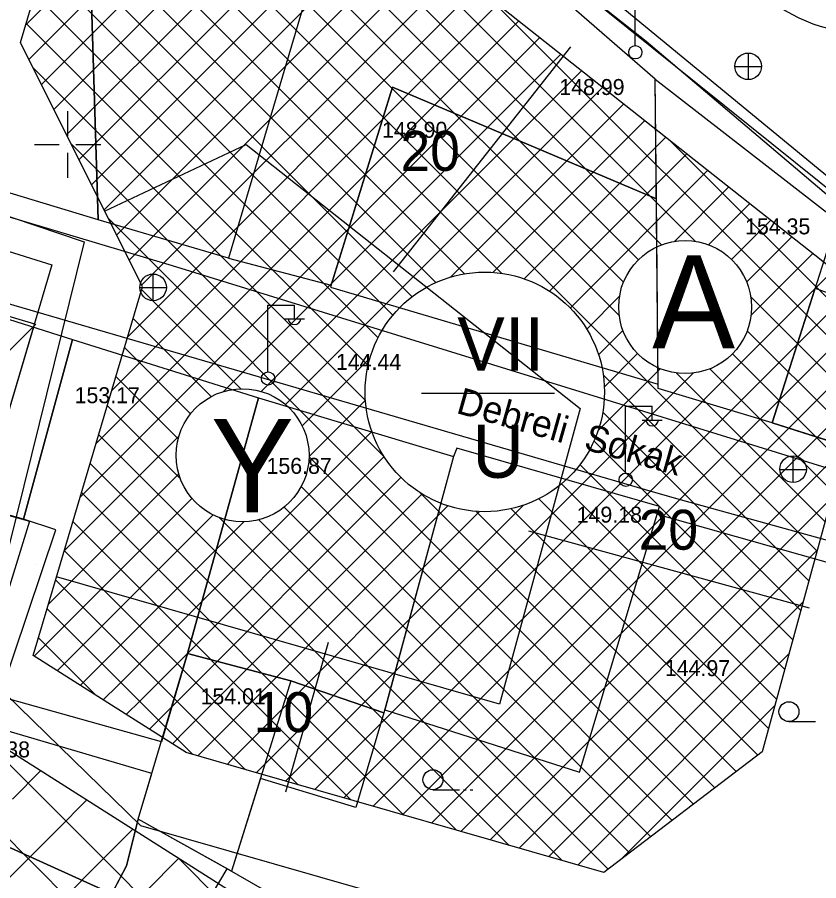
# Model space of a CAD drawing. Extents: x 419677 to 421689, y 4450851 to 4452923.
# Drawn here: x 420331.7 to 420392, y 4452030.4 to 4452095.3 of the extents above; entities that cross this region are included whole.
import ezdxf

# ---------------------------------------------------------------- set-up
doc = ezdxf.new("R2010")
doc.units = 0
for name, color, linetype in [('AA_HH', 7, 'Continuous'), ('Level 10', 7, 'Continuous'), ('Level 15', 7, 'Continuous'), ('Level 20', 7, 'Continuous'), ('Level 27', 7, 'Continuous'), ('Level 28', 7, 'Continuous'), ('Level 29', 7, 'Continuous'), ('Level 30', 7, 'Continuous'), ('Level 34', 7, 'Continuous'), ('Level 62', 7, 'Continuous'), ('Level 9', 7, 'Continuous')]:
    doc.layers.add(name, color=color, linetype=linetype)

msp = doc.modelspace()

# ---------------------------------------------------------------- linework, layer by layer
at = {"layer": 'AA_HH'}
for p, q in [((420378.218, 4452093.193), (420378.218, 4452098.193)), ((420386.732, 4452090.608), (420386.732, 4452092.608)), ((420385.712, 4452091.598), (420387.712, 4452091.598)), ((420335.534, 4452088.236), (420335.534, 4452086.361)), ((420333.034, 4452085.736), (420334.909, 4452085.736)), ((420335.534, 4452085.736), (420335.534, 4452085.736)), ((420336.159, 4452085.736), (420338.034, 4452085.736)), ((420335.534, 4452085.111), (420335.534, 4452083.236)), ((420341.976, 4452073.996), (420341.976, 4452075.996)), ((420340.956, 4452074.986), (420342.956, 4452074.986)), ((420350.599, 4452068.677), (420350.599, 4452073.677)), ((420350.599, 4452073.677), (420352.599, 4452073.677)), ((420352.599, 4452072.677), (420352.599, 4452073.677)), ((420351.839, 4452072.637), (420353.339, 4452072.637)), ((420377.499, 4452061.071), (420377.499, 4452066.071)), ((420377.499, 4452066.071), (420379.499, 4452066.071)), ((420379.499, 4452065.071), (420379.499, 4452066.071)), ((420378.739, 4452065.031), (420380.239, 4452065.031)), ((420390.103, 4452060.335), (420390.103, 4452062.335)), ((420389.083, 4452061.325), (420391.083, 4452061.325)), ((420389.779, 4452042.367), (420391.779, 4452042.367)), ((420363.009, 4452037.254), (420365.009, 4452037.254)), ((420365.309, 4452037.254), (420365.509, 4452037.254)), ((420365.809, 4452037.254), (420366.009, 4452037.254))]:
    msp.add_line(p, q, dxfattribs=at)
for points in [[(420317.236, 4452103.177), (420337.405, 4452116.594), (420344.369, 4452120.618), (420344.658, 4452120.664), (420379.054, 4452093.495), (420408.951, 4452068.147), (420424.16, 4452057.043), (420424.384, 4452056.89), (420424.576, 4452056.652), (420424.822, 4452056.326), (420423.72, 4452053.785)], [(420405.725, 4452057.394), (420343.41, 4452076.627), (420303.176, 4452088.61), (420300.039, 4452090.002), (420299.731, 4452090.216), (420308.524, 4452096.729)], [(420320.09, 4452076.93), (420323.997, 4452075.844), (420379.577, 4452059.632), (420381.6, 4452059.053)], [(420381.6, 4452059.053), (420399.987, 4452053.987), (420401.611, 4452053.731), (420403.494, 4452054.063), (420405.385, 4452054.595), (420408.449, 4452053.543)], [(420379.876, 4452057.948), (420404.974, 4452050.876)]]:
    msp.add_lwpolyline(points, dxfattribs=at)
for points in [[(420336.801, 4452113.412), (420336.677, 4452115.141), (420345.277, 4452119.364), (420357.395, 4452110.063), (420347.626, 4452077.202), (420337.839, 4452080.08)], [(420336.801, 4452113.412), (420337.839, 4452080.08), (420317.631, 4452086.186), (420317.626, 4452103.064)], [(420379.725, 4452090.659), (420357.395, 4452110.063), (420347.626, 4452077.202), (420355.361, 4452075.177), (420359.957, 4452090.039), (420379.813, 4452081.648)], [(420379.725, 4452090.659), (420393.388, 4452080.065), (420388.529, 4452064.834), (420379.952, 4452067.409)], [(420359.957, 4452090.039), (420355.31, 4452075.014), (420379.949, 4452067.728), (420379.813, 4452081.648)], [(420405.557, 4452070.621), (420393.388, 4452080.065), (420388.529, 4452064.834), (420403.311, 4452060.104)], [(420335.913, 4452071.079), (420332.214, 4452057.576), (420317.998, 4452061.52), (420319.18, 4452065.5), (420321.989, 4452075.488)], [(420391.752, 4452074.937), (420395.561, 4452073.55), (420394.483, 4452068.454), (420397.254, 4452067.295), (420395.784, 4452062.512), (420388.529, 4452064.834)], [(420335.913, 4452071.079), (420349.89, 4452066.699), (420344.56, 4452047.485), (420342.586, 4452040.861), (420330.407, 4452044.249), (420334.656, 4452056.792), (420332.214, 4452057.576)], [(420344.56, 4452047.485), (420349.89, 4452066.699), (420364.542, 4452062.302), (420359.323, 4452043.025), (420352.308, 4452045.423)], [(420380.051, 4452058.528), (420364.807, 4452062.929), (420364.542, 4452062.302), (420359.385, 4452043.252), (420374.031, 4452038.582)], [(420332.672, 4452057.429), (420327.504, 4452040.743), (420314.771, 4452044.466), (420319.975, 4452060.971)], [(420357.202, 4452035.906), (420350.03, 4452038.086), (420347.869, 4452031.126), (420340.852, 4452035.042), (420340.852, 4452035.042), (420344.56, 4452047.485), (420352.308, 4452045.423), (420359.323, 4452043.025)], [(420344.56, 4452047.485), (420352.308, 4452045.423), (420347.869, 4452031.126), (420347.543, 4452031.315), (420340.852, 4452035.042)], [(420328.054, 4452042.52), (420327.504, 4452040.743), (420325.427, 4452033.582), (420331.288, 4452032.871), (420338.855, 4452029.424), (420339.966, 4452031.525), (420340.852, 4452035.042), (420341.876, 4452038.48)], [(420334.887, 4452018.168), (420349.19, 4452009.439), (420349.999, 4452010.924), (420350.986, 4452010.638), (420353.849, 4452027.662), (420347.543, 4452031.315), (420340.852, 4452035.042), (420339.966, 4452031.525), (420337.865, 4452027.552), (420334.327, 4452020.898), (420335.973, 4452020.049)], [(420340.852, 4452035.042), (420339.966, 4452031.525), (420337.865, 4452027.552), (420343.282, 4452024.138), (420347.543, 4452031.315)], [(420325.427, 4452033.582), (420322.994, 4452027.277), (420333.507, 4452020.339), (420334.327, 4452020.898), (420337.865, 4452027.552), (420338.855, 4452029.424), (420331.288, 4452032.871)]]:
    msp.add_lwpolyline(points, close=True, dxfattribs=at)
for centre, radius in [((420378.229, 4452092.668), 0.5), ((420386.717, 4452091.616), 1), ((420341.961, 4452075.004), 1), ((420350.609, 4452068.153), 0.5), ((420390.088, 4452061.343), 1), ((420377.509, 4452060.547), 0.5), ((420389.779, 4452043.117), 0.75), ((420363.009, 4452038.004), 0.75)]:
    msp.add_circle(centre, radius, dxfattribs=at)
for centre in [(420352.599, 4452072.681), (420379.499, 4452065.075)]:
    msp.add_arc(centre, 0.474, 184.83843, 355.14641, dxfattribs=at)
at = {"layer": 'Level 10'}
for points in [[(420408.198, 4452069.984), (420345.402, 4452120.383), (420315.25, 4452102.126), (420310.494, 4452088.921)], [(420310.312, 4452088.984), (420309.767, 4452087.535), (420336.779, 4452078.43), (420328.838, 4452046.411), (420341.019, 4452034.555), (420411.384, 4452014.406)]]:
    msp.add_lwpolyline(points, dxfattribs=at)
at = {"layer": 'Level 15'}
for p, q in [((420377.016, 4452072.879), (420337.597, 4452112.298)), ((420377.337, 4452075.387), (420341.191, 4452111.533)), ((420378.468, 4452077.084), (420345.211, 4452110.341)), ((420332.393, 4452094.738), (420347.359, 4452109.705)), ((420391.894, 4452055.173), (420336.951, 4452110.116)), ((420332.622, 4452092.14), (420349.541, 4452109.058)), ((420380.19, 4452078.191), (420349.231, 4452109.15)), ((420333.564, 4452090.253), (420351.722, 4452108.411)), ((420368.184, 4452076.055), (420336.304, 4452107.935)), ((420334.505, 4452088.366), (420353.66, 4452107.52)), ((420382.749, 4452078.46), (420353.8, 4452107.409)), ((420335.447, 4452086.479), (420355.24, 4452106.272)), ((420365.392, 4452076.018), (420335.657, 4452105.753)), ((420336.388, 4452084.592), (420356.82, 4452105.023)), ((420337.33, 4452082.705), (420358.4, 4452103.775)), ((420363.223, 4452075.359), (420335.011, 4452103.571)), ((420338.271, 4452080.818), (420359.98, 4452102.527)), ((420361.449, 4452074.304), (420334.364, 4452101.389)), ((420339.213, 4452078.931), (420361.56, 4452101.278)), ((420340.154, 4452077.044), (420363.14, 4452100.03)), ((420360.003, 4452072.922), (420333.717, 4452099.208)), ((420341.096, 4452075.157), (420364.72, 4452098.782)), ((420340.04, 4452071.273), (420366.3, 4452097.533)), ((420358.879, 4452071.218), (420333.071, 4452097.026)), ((420395.539, 4452068.499), (420367.273, 4452096.765)), ((420338.848, 4452067.253), (420367.88, 4452096.285)), ((420358.129, 4452069.139), (420332.424, 4452094.844)), ((420337.657, 4452063.233), (420369.46, 4452095.036)), ((420336.465, 4452059.213), (420371.04, 4452093.788)), ((420347.257, 4452067.177), (420372.621, 4452092.54)), ((420357.927, 4452066.511), (420332.943, 4452091.496)), ((420350.093, 4452067.184), (420374.201, 4452091.291)), ((420351.93, 4452066.192), (420375.781, 4452090.043)), ((420364.338, 4452075.772), (420377.361, 4452088.795)), ((420367.519, 4452076.125), (420378.941, 4452087.546)), ((420369.867, 4452075.644), (420380.521, 4452086.298)), ((420396.147, 4452070.719), (420380.745, 4452086.121)), ((420359.339, 4452062.272), (420335.76, 4452085.851)), ((420371.769, 4452074.719), (420382.101, 4452085.05)), ((420373.329, 4452073.45), (420383.681, 4452083.801)), ((420381.161, 4452078.453), (420385.261, 4452082.553)), ((420383.736, 4452078.2), (420386.841, 4452081.305)), ((420382.614, 4452036.169), (420338.577, 4452080.206)), ((420385.466, 4452077.1), (420388.421, 4452080.056)), ((420386.604, 4452075.411), (420390.001, 4452078.808)), ((420386.939, 4452072.918), (420391.581, 4452077.56)), ((420354.116, 4452037.266), (420393.161, 4452076.311)), ((420348.569, 4452067.385), (420341.101, 4452074.853)), ((420356.313, 4452036.635), (420394.742, 4452075.063)), ((420358.511, 4452036.004), (420396.322, 4452073.814)), ((420374.57, 4452071.862), (420377.042, 4452074.334)), ((420394.931, 4452066.278), (420386.915, 4452074.294)), ((420346.331, 4452066.795), (420340.455, 4452072.671)), ((420375.464, 4452069.928), (420377.295, 4452071.759)), ((420394.324, 4452064.057), (420386.646, 4452071.735)), ((420360.708, 4452035.373), (420396.181, 4452070.846)), ((420344.786, 4452065.512), (420339.808, 4452070.49)), ((420375.897, 4452067.532), (420378.395, 4452070.03)), ((420393.716, 4452061.836), (420385.539, 4452070.013)), ((420353.17, 4452064.603), (420358.278, 4452069.711)), ((420375.417, 4452064.224), (420380.084, 4452068.891)), ((420393.109, 4452059.615), (420383.842, 4452068.882)), ((420343.844, 4452063.625), (420339.161, 4452068.308)), ((420351.919, 4452037.897), (420382.578, 4452068.556)), ((420391.286, 4452052.953), (420375.814, 4452068.425)), ((420392.501, 4452057.394), (420381.334, 4452068.561)), ((420362.906, 4452034.742), (420395.116, 4452066.952)), ((420344.004, 4452060.636), (420338.514, 4452066.126)), ((420353.687, 4452062.292), (420357.926, 4452066.531)), ((420390.678, 4452050.732), (420375.777, 4452065.633)), ((420339.303, 4452045.081), (420358.406, 4452064.184)), ((420335.273, 4452055.192), (420343.897, 4452063.817)), ((420368.748, 4452033.064), (420337.868, 4452063.945)), ((420390.071, 4452048.511), (420375.118, 4452063.464)), ((420365.103, 4452034.111), (420394.051, 4452063.058)), ((420341.011, 4452043.96), (420359.333, 4452062.282)), ((420381.009, 4452034.946), (420353.687, 4452062.267)), ((420364.78, 4452034.203), (420337.221, 4452061.763)), ((420389.463, 4452046.29), (420374.063, 4452061.69)), ((420334.081, 4452051.172), (420343.89, 4452060.981)), ((420342.718, 4452042.839), (420360.601, 4452060.722)), ((420388.856, 4452044.069), (420372.681, 4452060.244)), ((420360.813, 4452035.343), (420336.574, 4452059.581)), ((420379.404, 4452033.722), (420353.097, 4452060.029)), ((420384.218, 4452037.393), (420362.031, 4452059.58)), ((420334.673, 4452048.935), (420344.882, 4452059.144)), ((420344.426, 4452041.718), (420362.189, 4452059.481)), ((420367.3, 4452033.48), (420392.985, 4452059.165)), ((420388.248, 4452041.848), (420370.977, 4452059.12)), ((420346.134, 4452040.598), (420364.123, 4452058.587)), ((420349.721, 4452038.528), (420369.828, 4452058.634)), ((420377.799, 4452032.498), (420351.814, 4452058.483)), ((420387.428, 4452039.84), (420368.898, 4452058.37)), ((420335.888, 4452047.321), (420346.471, 4452057.904)), ((420372.716, 4452031.924), (420346.938, 4452057.702)), ((420347.842, 4452039.477), (420366.519, 4452058.154)), ((420385.823, 4452038.616), (420366.27, 4452058.168)), ((420356.845, 4452036.482), (420335.927, 4452057.399)), ((420337.595, 4452046.201), (420348.781, 4452057.387)), ((420376.194, 4452031.275), (420349.926, 4452057.542)), ((420352.877, 4452037.622), (420335.281, 4452055.218)), ((420369.498, 4452032.849), (420391.92, 4452055.271)), ((420348.863, 4452038.807), (420334.634, 4452053.036)), ((420371.695, 4452032.218), (420390.855, 4452051.377)), ((420334.001, 4452050.84), (420333.987, 4452050.854)), ((420340.633, 4452044.208), (420334.001, 4452050.84)), ((420333.026, 4452047.288), (420334.673, 4452048.935)), ((420337.67, 4452044.344), (420333.34, 4452048.673)), ((420334.757, 4452046.19), (420335.888, 4452047.321)), ((420335.888, 4452047.321), (420335.888, 4452047.321)), ((420373.893, 4452031.587), (420389.79, 4452047.484)), ((420336.487, 4452045.093), (420337.595, 4452046.201)), ((420337.595, 4452046.201), (420337.595, 4452046.201)), ((420338.218, 4452043.996), (420339.303, 4452045.081)), ((420339.949, 4452042.898), (420341.011, 4452043.96)), ((420344.941, 4452039.901), (420340.635, 4452044.206)), ((420377.098, 4452031.964), (420388.725, 4452043.59)), ((420341.68, 4452041.801), (420342.718, 4452042.839)), ((420342.718, 4452042.839), (420342.718, 4452042.839)), ((420343.411, 4452040.703), (420344.426, 4452041.718)), ((420344.426, 4452041.718), (420344.426, 4452041.718)), ((420345.326, 4452039.79), (420346.134, 4452040.598)), ((420347.524, 4452039.159), (420347.842, 4452039.477)), ((420348.909, 4452038.761), (420348.863, 4452038.807))]:
    msp.add_line(p, q, dxfattribs=at)
at = {"layer": 'Level 20'}
for p, q in [((420373.362, 4452093.072), (420360.007, 4452076.168)), ((420338.319, 4452080.722), (420348.968, 4452085.738)), ((420348.968, 4452085.738), (420374.09, 4452065.89)), ((420374.09, 4452065.89), (420368.013, 4452043.68)), ((420391.331, 4452050.901), (420370.228, 4452056.675)), ((420368.013, 4452043.68), (420334.697, 4452053.248)), ((420351.937, 4452037.097), (420355.164, 4452048.335))]:
    msp.add_line(p, q, dxfattribs=at)
at = {"layer": 'Level 27'}
for points in [[(420322.329, 4452075.448), (420333.035, 4452072.273)], [(420322.329, 4452075.448), (420333.035, 4452072.273)], [(420336.491, 4452071.246), (420336.491, 4452071.246)], [(420336.491, 4452071.246), (420336.491, 4452071.246)]]:
    msp.add_lwpolyline(points, dxfattribs=at)
at = {"layer": 'Level 28'}
for points in [[(420333.991, 4452050.868), (420341.156, 4452075.037), (420331.995, 4452093.397), (420337.679, 4452112.574)], [(420396.874, 4452073.378), (420387.77, 4452040.101), (420375.862, 4452031.021), (420348.952, 4452038.749)], [(420333.035, 4452072.273), (420324.731, 4452044.259), (420348.308, 4452029.309)], [(420333.035, 4452072.273), (420324.731, 4452044.259), (420348.308, 4452029.309)], [(420348.951, 4452038.749), (420344.459, 4452040.039), (420332.945, 4452047.339), (420333.991, 4452050.868)]]:
    msp.add_lwpolyline(points, dxfattribs=at)
at = {"layer": 'Level 29'}
msp.add_lwpolyline([(420337.679, 4452112.574), (420353.018, 4452108.027), (420396.874, 4452073.378)], dxfattribs=at)
at = {"layer": 'Level 30'}
msp.add_line((420372.145, 4452067.036), (420362.145, 4452067.036), dxfattribs=at)
for centre, radius in [((420381.975, 4452073.52), 5), ((420366.905, 4452067.146), 9), ((420348.688, 4452062.386), 5)]:
    msp.add_circle(centre, radius, dxfattribs=at)
at = {"layer": 'Level 34'}
for p, q in [((420322.114, 4452061.215), (420333.141, 4452072.242)), ((420322.114, 4452061.215), (420333.141, 4452072.242)), ((420356.495, 4452008.155), (420304.761, 4452059.888)), ((420356.495, 4452008.155), (420304.761, 4452059.888)), ((420333.118, 4452054.158), (420333.118, 4452054.158)), ((420333.118, 4452054.158), (420333.118, 4452054.158)), ((420339.024, 4452031.282), (420328.327, 4452041.979)), ((420339.024, 4452031.282), (420328.327, 4452041.979)), ((420331.388, 4452036.548), (420333.524, 4452038.684)), ((420331.388, 4452036.548), (420333.524, 4452038.684)), ((420334.736, 4452034.239), (420336.985, 4452036.489)), ((420334.736, 4452034.239), (420336.985, 4452036.489)), ((420325.96, 4452025.463), (420334.736, 4452034.239)), ((420325.96, 4452025.463), (420334.736, 4452034.239)), ((420338.084, 4452031.93), (420340.447, 4452034.293)), ((420338.084, 4452031.93), (420340.447, 4452034.293)), ((420329.409, 4452023.255), (420338.084, 4452031.93)), ((420329.409, 4452023.255), (420338.084, 4452031.93)), ((420341.432, 4452029.621), (420343.909, 4452032.098)), ((420341.432, 4452029.621), (420343.909, 4452032.098)), ((420349.717, 4452026.246), (420343.787, 4452032.176)), ((420349.717, 4452026.246), (420343.787, 4452032.176)), ((420364.397, 4452005.909), (420339.024, 4452031.282)), ((420364.397, 4452005.909), (420339.024, 4452031.282))]:
    msp.add_line(p, q, dxfattribs=at)
at = {"layer": 'Level 62'}
msp.add_line((420408.658, 4452070.167), (420355.096, 4452114.255), dxfattribs=at)
msp.add_arc((420395.699, 4452106.09), 12, 230.54342, 274.86308, dxfattribs=at)
at = {"layer": 'Level 9'}
msp.add_line((420308.69, 4452084.802), (420334.345, 4452076.692), dxfattribs=at)
msp.add_line((420308.69, 4452084.802), (420334.345, 4452076.692), dxfattribs=at)
msp.add_line((420308.69, 4452084.802), (420334.345, 4452076.692), dxfattribs=at)
msp.add_lwpolyline([(420334.345, 4452076.692), (420324.731, 4452044.259), (420348.309, 4452029.309)], dxfattribs=at)
msp.add_lwpolyline([(420334.345, 4452076.692), (420324.731, 4452044.259), (420348.309, 4452029.309)], dxfattribs=at)
msp.add_lwpolyline([(420334.345, 4452076.692), (420324.731, 4452044.259), (420348.309, 4452029.309)], dxfattribs=at)

# ---------------------------------------------------------------- texts
at = {"layer": 'AA_HH'}
for s, p in [('148.99 ', (420372.511, 4452089.46)), ('148.90', (420359.18, 4452086.243)), ('154.35 ', (420386.479, 4452078.988)), ('153.17', (420336.061, 4452066.3)), ('156.87', (420350.492, 4452060.989)), ('149.18', (420373.817, 4452057.322)), ('154.01', (420345.533, 4452043.672)), ('152.38', (420327.798, 4452039.682))]:
    msp.add_text(s, height=1.2, dxfattribs=at).set_placement(p)
for s, height, rotation, p in [('144.44 ', 1.2, 0.00255, (420355.712, 4452068.803)), ('Debreli  Sokak', 2, 344.16984, (420364.68, 4452065.582)), ('144.97 ', 1.2, 0.00255, (420380.45, 4452045.79))]:
    msp.add_text(s, height=height, rotation=rotation, dxfattribs=at).set_placement(p)
at = {"layer": 'Level 20'}
for s, p in [('20', (420360.567, 4452083.759)), ('20', (420378.481, 4452055.289)), ('10', (420349.533, 4452041.588))]:
    msp.add_text(s, height=3, dxfattribs=at).set_placement(p)
at = {"layer": 'Level 30'}
for s, height, p in [('A', 7, (420379.489, 4452070.41)), ('VII', 4, (420364.841, 4452068.743)), ('Y', 7, (420346.31, 4452058.099)), ('U', 4, (420365.975, 4452060.693))]:
    msp.add_text(s, height=height, dxfattribs=at).set_placement(p)

doc.saveas('drawing.dxf')
